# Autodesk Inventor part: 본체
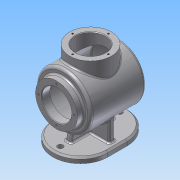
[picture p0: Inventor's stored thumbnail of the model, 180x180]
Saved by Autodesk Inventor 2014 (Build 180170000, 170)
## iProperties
Created: 2016-04
Part Number: 본체
Material: 알루미늄 6061
Document SubType Name: Modeling
Designer: 601-
Density: 2.71 g/cm^3
Appearance: 알루미늄 - 평지
Mass: 1195.29 g
Surface Area: 1196.97 cm^2
Volume: 441.067 cm^3
Author: 601-
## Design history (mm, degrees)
sketch "스케치2"
  geometry: L1 (-17.5, 0)-(17.5, 0); L2 (-17.5, -50)-(17.5, -50); L3 (17.5, 50)-(-17.5, 50); L4 (-67.5, 0)-(67.5, 0); L5 (0, 50)-(0, -50); A1 r 50 centre (-17.5, 0) between (-17.5, 50) and (-17.5, -50); A2 r 50 centre (17.5, 0) between (17.5, -50) and (17.5, 50); 1 further point
  constraints: 12 end point, 6 point on circle, 4 tangent, 3 midpoint, 2 centre point, 1 horizontal, 1 parallel
  dimensions: "d0" = 135 distance of L4.end L4.start; "d1" = 100 distance of L5.end L5.start
extrude "돌출1" new body sketch "스케치2" distance "d2" = 10; taper "d3" = 0 deg
sketch "스케치3"
  geometry: L1 (0, -67.5)-(0, 67.5); C1 r 5 at (0, -54); C2 r 5 at (0, 54); A1 r 50 centre (0, 17.5) between (50, 17.5) and (-50, 17.5) reference; A2 r 50 centre (0, -17.5) between (-50, -17.5) and (50, -17.5) reference; 1 further point
  constraints: 2 centre point, 2 end point, 2 point on circle, 2 point on line, 1 equal radius
  dimensions: "d4" = 10 diameter of C1; "d5" = 108 distance of C2.centre C1.centre; "d6" = 54 distance of point (0, 0) C1.centre
extrude "돌출2" cut sketch "스케치3" stored distance "d7" = 10; taper "d8" = 0 deg
sketch "스케치5"
  geometry: L1 (0, 0)-(79, 0); L2 (0, -17.5)-(0, 17.5) reference; L3 (79, 61)-(79, -61); L4 (79, 61)-(117, 61); L5 (117, 61)-(117, 49); L6 (117, 49)-(79, 49); L7 (79, 49)-(79, 61); L8 (79, 49)-(129, 49); L9 (129, 49)-(129, -51); L10 (79, -49)-(79, 49); L11 (79, -49)-(79, -61); L12 (79, -49)-(79, -61); L13 (79, -51)-(79, -61); L14 (79, -51)-(129, -51); L15 (79, 49)-(129, 49); L16 (129, 49)-(129, -51); L17 (129, -51)-(79, -51); L18 (79, -51)-(79, 49); L19 (129, -51)-(79, -51); L20 (0, 67.5)-(10, 67.5) reference; L21 (0, -67.5)-(10, -67.5) reference; A1 r 120 centre (81.003, 58.983) between (79, -61) and (129, -51)
  constraints: 36 end point, 6 parallel, 5 perpendicular, 4 collinear, 3 horizontal, 2 midpoint, 2 point on circle, 1 centre point, 1 point on line
  dimensions: "d19" = 79 distance of L1.end L1.start; "d21" = 12 distance of L4.end L5.end; "d22" = 100 diameter of L9 L3; "d23" = 76 diameter of L5 L3; "d25" = 122 distance from line of L12.end L4; "d28" = 120 radius of A1; "d41" = 61 distance from line of L1.end L4
revolve "회전1" stored, may be unused: angle "d29" = 90 deg
revolve "회전2" stored, may be unused: angle "d30" = 90 deg
sketch "스케치8"
  geometry: L1 (-40, 5)-(40, 5); L2 (40, 5)-(40, -5); L3 (40, -5)-(-40, -5); L4 (-40, -5)-(-40, 5); L5 (-40, 5)-(40, -5); L6 (40, 5)-(-40, -5); 1 further point
  constraints: 12 end point, 2 midpoint, 2 parallel, 1 horizontal, 1 perpendicular
  dimensions: "d37" = 80 distance of L1.start L1.end; "d38" = 10 distance of L1.end L2.end
extrude "돌출4" join sketch "스케치8" stored distance "d39" = 10; taper "d40" = 0 deg
sketch "스케치9"
  geometry: L1 (10, 67.5)-(10, 59) reference; L2 (10, 59)-(0, 59) reference; L3 (0, 59)-(0, 67.5) reference; L4 (0, 67.5)-(10, 67.5) reference; L5 (10, -67.5)-(0, -67.5) reference; L6 (0, -67.5)-(0, -59) reference; L7 (0, -59)-(10, -59) reference; L8 (10, -59)-(10, -67.5) reference; L9 (41, 61)-(117, 61) reference; L10 (117, 61)-(117, 49) reference; L11 (117, 49)-(129, 49) reference; L12 (129, 49)-(129, -51) reference; L13 (29, -51)-(29, -5) reference; L14 (10, -5)-(10, -49) reference; L15 (10, -49)-(0, -49) reference; L16 (0, -49)-(0, 49) reference; L17 (0, 49)-(10, 49) reference; L18 (10, 49)-(10, 5) reference; L19 (29, 5)-(29, 49) reference; L20 (29, 49)-(41, 49) reference; L21 (41, 49)-(41, 61) reference; L22 (41, 61)-(117, 61) reference; L23 (79, 46)-(79, -58); L24 (32, -49.018)-(32, 46); L25 (32, 46)-(79, 46); L26 (29, -5)-(10, -5) reference; L27 (10, 5)-(29, 5) reference; A1 r 120 centre (81.003, 58.983) between (79, -61) and (129, -51) reference; A2 r 120 centre (76.997, 58.983) between (29, -51) and (79, -61) reference; A3 r 117 centre (76.997, 58.983) between (32, -49.018) and (79, -58); 1 further point
  constraints: 6 end point, 2 point on circle, 2 symmetric about line, 1 centre point, 1 perpendicular
  dimensions: "d132" = 3 distance between parallel lines of L13 L24
revolve "회전3" sketch "스케치9" stored, may be unused: angle "d46" = 90 deg
sketch "스케치10"
  geometry: C1 r 38 at (0, 0) reference; C2 r 27 at (0, 0); 1 further point
  constraints: 1 centre point, 1 coincident
  dimensions: "d47" = 54 diameter of C2
extrude "돌출5" cut sketch "스케치10" distance "d48" = 15; taper "d49" = 0 deg
sketch "스케치11" dims "d50" = 65
  geometry: C1 r 38 at (0, 0) reference; 3 further points
  constraints: 1 coincident, 1 horizontal alignment, 2 other
hole "구멍1" sketch "스케치11" at (32.5, 0) diameter "d51" = 3.242; stored, may be unused: countersink angle "d55" = 90 deg, drill point angle "d57" = 118 deg; dims "d52" = 8, "d53" = 4, "d54" = 2, "d56" = 10
node "작업 평면2"
sketch "스케치12"
  geometry: L1 (49, 50)-(49, -50) reference; C1 r 38 at (-1, 0); 1 further point
  constraints: 1 centre point
  dimensions: "d102" = 50 distance from line of L1 C1.centre; "d103" = 76 diameter of C1
extrude "돌출6" join sketch "스케치12" stored distance "d63" = 10; taper "d64" = 0 deg
chamfer "모따기1" distance "d89" = 3; stored, may be unused: second distance "d90" = 2, angle "d91" = 45 deg
fillet "모깎기4" dims "d92" = 3
fillet "모깎기6" dims "d94" = 5, "d95" = 2
chamfer "모따기2" distance "d96" = 1; stored, may be unused: second distance "d97" = 2, angle "d98" = 45 deg
sketch "스케치16"
  geometry: L1 (107, 61)-(51, 61) reference; L2 (79, 61)-(79, -71.856); 1 further point
  constraints: 2 end point, 1 midpoint, 1 perpendicular
fillet "모깎기7" dims "d101" = 3
sketch "스케치18"
  geometry: C1 r 38 at (0, 0) reference; C2 r 27 at (0, 0); 1 further point
  constraints: 1 centre point, 1 coincident
  dimensions: "d104" = 54 diameter of C2
extrude "돌출8" cut sketch "스케치18" stored distance "d105" = 10; taper "d106" = 0 deg
sketch "스케치19" dims "d107" = 65
  geometry: C1 r 38 at (0, 0) reference; 3 further points
  constraints: 1 coincident, 1 vertical alignment, 2 other
hole "구멍4" sketch "스케치19" at (0, 32.5) diameter "d108" = 3.242; stored, may be unused: countersink angle "d112" = 90 deg, drill point angle "d114" = 118 deg; dims "d109" = 8, "d110" = 4, "d111" = 2, "d113" = 10
fillet "모깎기8" dims "d118" = 3
chamfer "모따기3" distance "d119" = 1; stored, may be unused: second distance "d120" = 2, angle "d121" = 45 deg
sketch "스케치20"
  geometry: L1 (52, 60)-(106, 60) reference; L2 (79, 60)-(79, -71.197); 1 further point
  constraints: 2 end point, 1 midpoint, 1 perpendicular
node "작업 평면5"
sketch "스케치21"
  geometry: C1 r 50 at (0, 0) reference; 2 further points
  constraints: 1 coincident, 1 other
feature "엠보싱2" sketch "스케치21" dims "d0" = 135, "d1" = 100, "d7" = 10, "d8" = 0, "d122" = 0.5, "d123" = 0
sketch "스케치22"
  geometry: L1 (10, 64.5)-(10, 17.5) reference; L2 (10, -17.5)-(10, -64.5) reference; L3 (10, 40)-(30.809, 36.331); L4 (30.809, 36.331)-(30.809, -36.331); L5 (30.809, -36.331)-(10, -40); L6 (10, 40)-(10, -40); L7 (0, 0)-(62.313, 0); L8 (49, -2)-(10, -2) reference; 2 further points
  constraints: 10 end point, 2 parallel, 2 point on line, 1 collinear
  dimensions: "d124" = 40 distance from line of L7 L3.start; "d125" = 40 distance from line of L5.end L7; "d126" = 100 deg angle of L1 L3; "d127" = 100 deg angle of L2 L5
extrude "돌출9" join sketch "스케치22" stored distance "d128" = 10; taper "d129" = 0 deg
fillet "모깎기9" dims "d130" = 3
fillet "모깎기10" dims "d131" = 3
node "솔리드1"
pattern_circular "원형 패턴1" dims angle "d59" = 360 deg
pattern_circular "원형 패턴3" dims angle "d116" = 360 deg
node "절단 모서리 투영1"
other parameters: "d61" = 144
